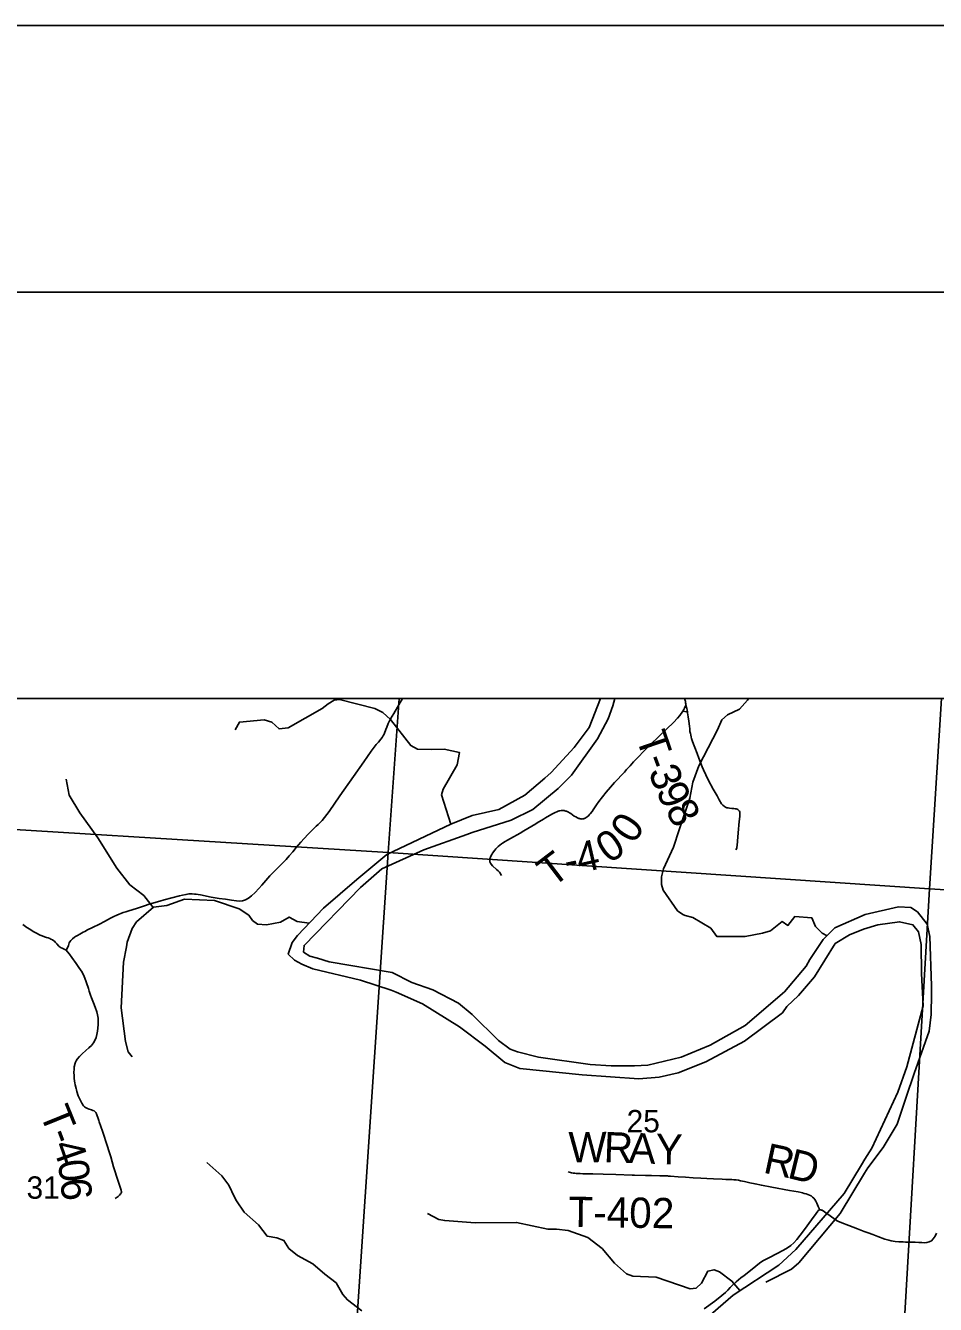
# Model space of a CAD drawing. Extents: x 396.2 to 468.4, y 232.6 to 279.1.
# Drawn here: x 416.062 to 417.769, y 276.722 to 279.121 of the extents above; entities that cross this region are included whole.
import ezdxf

# ---------------------------------------------------------------- set-up
doc = ezdxf.new("R2010")
doc.units = 0
for name, color, linetype in [('Default', 7, 'Continuous'), ('GM_X_Major_River', 7, 'Continuous'), ('GM_X_Minor_River', 7, 'Continuous'), ('GM_X_Section', 7, 'Continuous'), ('GM_X_Section_Text', 7, 'Continuous'), ('GM_X_Township_Road', 7, 'Continuous'), ('GM_X_Township_Road_Text', 7, 'Continuous'), ('SH_Border', 7, 'Continuous'), ('SH_Cut_Line', 7, 'Continuous'), ('TX_P_1', 7, 'Continuous')]:
    doc.layers.add(name, color=color, linetype=linetype)

msp = doc.modelspace()

# ---------------------------------------------------------------- linework, layer by layer
at = {"layer": 'Default'}
msp.add_lwpolyline([(421.9682, 277.8582), (415.7353, 277.8582), (415.7264, 277.732), (415.6501, 276.6818)], dxfattribs=at)
for points in [[(416.7632, 277.8582), (415.744, 277.8582), (415.7301, 277.667), (415.7271, 277.6318), (416.7426, 277.5691)], [(417.7799, 277.8582), (416.7632, 277.8582), (416.7426, 277.5691), (417.7578, 277.5012)], [(418.5596, 277.8582), (417.7799, 277.8582), (417.7578, 277.5012), (418.7866, 277.4374), (418.8114, 277.8417)]]:
    msp.add_lwpolyline(points, close=True, dxfattribs=at)
at = {"layer": 'GM_X_Major_River'}
for points in [[(417.1403, 277.8582), (417.1194, 277.8041), (417.0911, 277.7661), (417.048, 277.7192), (417.036, 277.7086), (416.9989, 277.6769), (416.9501, 277.6498), (416.8998, 277.6386), (416.8601, 277.6225), (416.7398, 277.5655), (416.6834, 277.5187), (416.6211, 277.4649), (416.5724, 277.4135), (416.5626, 277.4006), (416.5551, 277.3785), (416.5664, 277.3672), (416.5805, 277.3597), (416.601, 277.351), (416.6908, 277.3297), (416.7477, 277.3109), (416.7575, 277.3072), (416.8065, 277.2857), (416.8763, 277.2424), (416.9245, 277.2057), (416.9613, 277.1755), (416.989, 277.1642), (417.1065, 277.1525), (417.2122, 277.1449), (417.2504, 277.1481), (417.2864, 277.1562), (417.3382, 277.1765), (417.4105, 277.2155), (417.4819, 277.2685), (417.4902, 277.2807)], [(417.7612, 277.3047), (417.7613, 277.3193), (417.7584, 277.4115), (417.7534, 277.4347), (417.7352, 277.4577), (417.7227, 277.466), (417.6995, 277.4671), (417.6371, 277.4532), (417.5803, 277.4279), (417.5584, 277.4058), (417.5332, 277.3685), (417.526, 277.356), (417.4856, 277.308), (417.4119, 277.2448), (417.3465, 277.2077), (417.292, 277.1855), (417.2296, 277.1704), (417.2046, 277.1688), (417.1606, 277.1694), (417.1212, 277.1715), (417.0242, 277.1856), (416.9852, 277.1953), (416.9711, 277.2006), (416.9491, 277.2168), (416.9001, 277.2652), (416.8743, 277.2867), (416.8261, 277.3116), (416.787, 277.3255), (416.7499, 277.344), (416.6316, 277.364), (416.61, 277.3708), (416.5952, 277.3749), (416.5838, 277.3824), (416.5846, 277.395), (416.6907, 277.5035), (416.7304, 277.5389), (416.8091, 277.5745), (416.89, 277.6033), (416.8999, 277.6067), (416.9733, 277.6298), (417.0138, 277.65), (417.0614, 277.6893), (417.0859, 277.7144), (417.135, 277.7826), (417.155, 277.8198), (417.164, 277.8445), (417.1677, 277.8582)], [(417.4902, 277.2807), (417.5118, 277.3009), (417.542, 277.3363), (417.5808, 277.3983), (417.6073, 277.4151), (417.6338, 277.4255), (417.661, 277.4335), (417.7015, 277.4394), (417.7265, 277.4338), (417.7368, 277.4206), (417.7422, 277.3967), (417.7427, 277.342), (417.7459, 277.2817), (417.7148, 277.1674), (417.6983, 277.1195), (417.6493, 277.0149), (417.6361, 276.994), (417.6301, 276.9834), (417.5973, 276.9294), (417.5067, 276.8243), (417.4749, 276.7953), (417.3895, 276.7388), (417.3283, 276.6855)], [(417.7139, 277.1102), (417.7288, 277.1549), (417.757, 277.2339), (417.7607, 277.2651), (417.7612, 277.3047)], [(417.4504, 276.763), (417.4985, 276.7878), (417.5124, 276.7993), (417.5902, 276.8921), (417.6354, 276.9675), (417.6422, 276.9777), (417.6709, 277.0158), (417.6969, 277.0595), (417.7139, 277.1102)]]:
    msp.add_lwpolyline(points, dxfattribs=at)
at = {"layer": 'GM_X_Minor_River'}
for points in [[(416.8601, 277.6225), (416.8426, 277.6772), (416.8454, 277.6882), (416.8719, 277.7338), (416.8764, 277.7566), (416.8472, 277.763), (416.8229, 277.7626), (416.7971, 277.763), (416.7847, 277.77), (416.747, 277.8191), (416.7323, 277.8319), (416.7173, 277.8397), (416.6514, 277.8561), (416.6408, 277.8548), (416.6296, 277.8481), (416.6185, 277.8395), (416.5546, 277.8031), (416.5378, 277.8011), (416.5243, 277.8138), (416.5099, 277.8182), (416.4635, 277.8139), (416.4554, 277.7995)], [(417.5656, 277.4132), (417.5562, 277.4181), (417.5436, 277.4307), (417.5372, 277.4466), (417.505, 277.4492), (417.4921, 277.4325), (417.4811, 277.4397), (417.4595, 277.4222), (417.4443, 277.418), (417.4117, 277.4115), (417.3655, 277.4118), (417.3587, 277.4118), (417.3473, 277.4274), (417.3136, 277.4471), (417.2995, 277.4509), (417.295, 277.4528), (417.2851, 277.46), (417.2582, 277.4984), (417.2548, 277.509), (417.2552, 277.5234), (417.2586, 277.5387), (417.2772, 277.579), (417.2879, 277.6121), (417.3083, 277.6714), (417.3137, 277.7015), (417.3247, 277.7319), (417.3603, 277.7996), (417.3683, 277.8183), (417.3789, 277.8278), (417.4013, 277.8381), (417.4164, 277.8552), (417.4181, 277.8582)], [(416.3018, 277.4661), (416.2841, 277.4885), (416.2579, 277.5086), (416.2333, 277.5398), (416.1977, 277.5968), (416.164, 277.6439), (416.1439, 277.6769), (416.1386, 277.707)], [(416.5941, 277.4366), (416.5718, 277.4398), (416.5566, 277.4481), (416.5407, 277.4386), (416.5141, 277.4336), (416.4975, 277.4347), (416.488, 277.4416), (416.4808, 277.4518), (416.463, 277.4636), (416.4164, 277.4795), (416.3603, 277.4817), (416.3273, 277.4699), (416.3022, 277.4665), (416.2704, 277.4391), (416.2621, 277.4265), (416.2526, 277.401), (416.2514, 277.3923), (416.2461, 277.3638), (416.2419, 277.2778), (416.2498, 277.2147), (416.2548, 277.1953), (416.2623, 277.1858)], [(416.6932, 276.7095), (416.6663, 276.73), (416.6572, 276.7403), (416.6451, 276.7619), (416.6238, 276.7782), (416.6011, 276.7976), (416.5723, 276.8132), (416.556, 276.8265), (416.5469, 276.8417), (416.5336, 276.8462), (416.5154, 276.8496), (416.4995, 276.8709), (416.4726, 276.8944), (416.4582, 276.9161), (416.4544, 276.9225), (416.4435, 276.9453), (416.4302, 276.9628), (416.4022, 276.9875)], [(417.4017, 276.7479), (417.3869, 276.7654), (417.3636, 276.7828), (417.3537, 276.7864), (417.3419, 276.7842), (417.3302, 276.7616), (417.3198, 276.7519), (417.3088, 276.7509), (417.2449, 276.7726), (417.2013, 276.7744), (417.1896, 276.7787), (417.167, 276.7988), (417.1439, 276.8264), (417.1168, 276.8469), (417.0798, 276.86), (417.0578, 276.8626), (417.0415, 276.8628), (416.9832, 276.8753), (416.9053, 276.8745), (416.8484, 276.8787), (416.8374, 276.8811), (416.8163, 276.892)]]:
    msp.add_lwpolyline(points, dxfattribs=at)
at = {"layer": 'GM_X_Section'}
for points in [[(415.7271, 277.6318), (416.7426, 277.5691), (416.6739, 276.5403), (415.6539, 276.603), (415.6579, 276.653)], [(417.7578, 277.5012), (417.6982, 276.4784), (416.6739, 276.5403), (416.7426, 277.5691)], [(417.7578, 277.5012), (418.7866, 277.4374), (418.7224, 276.4162), (417.6982, 276.4784)]]:
    msp.add_lwpolyline(points, close=True, dxfattribs=at)
at = {"layer": 'GM_X_Township_Road'}
for points in [[(416.0573, 277.4341), (416.0649, 277.4288), (416.0703, 277.4253), (416.0765, 277.4214), (416.0804, 277.4193), (416.0841, 277.4174), (416.0874, 277.4155), (416.0895, 277.4145), (416.0932, 277.4129), (416.0978, 277.4112), (416.1017, 277.4101), (416.1049, 277.4091), (416.1078, 277.4079), (416.11, 277.4069), (416.1129, 277.4053), (416.1152, 277.4038), (416.117, 277.4022), (416.1185, 277.4005), (416.121, 277.3979), (416.1248, 277.3938), (416.1281, 277.3911), (416.1308, 277.3897), (416.1383, 277.3861), (416.1408, 277.3906), (416.1427, 277.395), (416.1433, 277.3972), (416.1444, 277.3998), (416.1455, 277.4019), (416.1471, 277.4043), (416.1491, 277.4063), (416.1505, 277.4076), (416.1543, 277.4105), (416.1558, 277.4115), (416.1598, 277.4139), (416.1642, 277.4163), (416.1706, 277.4197), (416.1736, 277.4213), (416.1785, 277.424), (416.1878, 277.4289), (416.2009, 277.435), (416.2105, 277.4398), (416.2216, 277.4458), (416.2279, 277.4494), (416.2333, 277.452), (416.2377, 277.4537), (416.2413, 277.4551), (416.2454, 277.4567), (416.2502, 277.4582), (416.2563, 277.4601), (416.2701, 277.4643), (416.2855, 277.4695), (416.2942, 277.4724), (416.3141, 277.4783), (416.3221, 277.4804), (416.351, 277.4877), (416.3569, 277.4893), (416.3635, 277.4907), (416.3685, 277.4915), (416.3721, 277.4917), (416.3747, 277.4917), (416.3789, 277.4914), (416.3821, 277.4909), (416.3858, 277.4904), (416.3902, 277.4896), (416.4103, 277.4856), (416.4256, 277.4831), (416.4373, 277.4815), (416.4484, 277.4799), (416.4582, 277.4786), (416.4637, 277.4782), (416.4692, 277.4788), (416.4749, 277.4807), (416.4802, 277.4838), (416.4861, 277.4882), (416.4929, 277.4945), (416.4997, 277.5016), (416.5055, 277.5081), (416.5128, 277.5165), (416.5207, 277.5253), (416.528, 277.533), (416.5425, 277.5475), (416.5486, 277.5537), (416.5512, 277.5563), (416.5569, 277.5628), (416.5637, 277.5708), (416.5701, 277.5784), (416.5789, 277.5888), (416.5851, 277.5958), (416.5923, 277.6035), (416.6023, 277.6137), (416.6073, 277.6185), (416.6109, 277.6218), (416.6188, 277.6296), (416.6232, 277.6348), (416.6316, 277.6461), (416.652, 277.6758), (416.6772, 277.7118), (416.6966, 277.7396), (416.7105, 277.7594), (416.7201, 277.7717), (416.724, 277.7765), (416.7288, 277.7822), (416.7309, 277.785), (416.7326, 277.7876), (416.734, 277.7901), (416.7353, 277.793), (416.7362, 277.7951), (416.7374, 277.7983), (416.7379, 277.7998), (416.7396, 277.8047), (416.7423, 277.8111), (416.7466, 277.82), (416.7528, 277.8302), (416.7692, 277.8582)], [(417.108, 277.6323), (417.1088, 277.6325), (417.1098, 277.6328), (417.1108, 277.6331), (417.1116, 277.6335), (417.1138, 277.6349), (417.1153, 277.636), (417.1178, 277.6383), (417.1192, 277.6397), (417.1209, 277.6416), (417.1247, 277.6463), (417.1268, 277.6493), (417.1332, 277.6588), (417.1375, 277.6648), (417.1442, 277.6738), (417.1509, 277.6822), (417.1592, 277.6919), (417.1668, 277.7004), (417.1854, 277.7202), (417.1896, 277.7247), (417.1961, 277.7321), (417.2027, 277.7392), (417.2125, 277.7496), (417.2206, 277.7581), (417.229, 277.7663), (417.2352, 277.7724), (417.2496, 277.7866), (417.2647, 277.8011), (417.2773, 277.8133), (417.2848, 277.821), (417.2893, 277.8265), (417.295, 277.8345), (417.2968, 277.8376), (417.2979, 277.84), (417.3004, 277.846)], [(417.3004, 277.846), (417.3004, 277.8482), (417.3003, 277.8498), (417.3002, 277.8514), (417.3, 277.8523), (417.2997, 277.8537), (417.2993, 277.8546), (417.2986, 277.8562), (417.2977, 277.8577), (417.2974, 277.8582)], [(417.3946, 277.5741), (417.3954, 277.576), (417.3961, 277.5779), (417.3965, 277.5796), (417.3969, 277.5826), (417.3977, 277.5907), (417.3988, 277.6061), (417.4006, 277.6277), (417.4011, 277.6321), (417.4017, 277.6374), (417.4019, 277.6404), (417.402, 277.6434), (417.4017, 277.6452), (417.4012, 277.6466), (417.4008, 277.6473), (417.4001, 277.6483), (417.3994, 277.649), (417.3982, 277.6499), (417.3966, 277.6506), (417.395, 277.6511), (417.393, 277.6514), (417.3907, 277.6517), (417.3867, 277.6521), (417.3824, 277.6525), (417.3798, 277.6528), (417.3773, 277.6533), (417.3762, 277.6537), (417.3752, 277.6541), (417.3735, 277.6551), (417.3723, 277.656), (417.37, 277.658), (417.3678, 277.6609), (417.3633, 277.6683), (417.3594, 277.6753), (417.3521, 277.6883), (417.3426, 277.7056), (417.3379, 277.7151), (417.3339, 277.7241), (417.3312, 277.73), (417.3248, 277.746), (417.3216, 277.755), (417.3176, 277.7664), (417.3165, 277.7697), (417.3134, 277.7778), (417.3121, 277.781), (417.3113, 277.7834), (417.3108, 277.7854), (417.3097, 277.7899), (417.3092, 277.7924), (417.3084, 277.7965), (417.3079, 277.801), (417.3072, 277.8064), (417.3061, 277.8156), (417.305, 277.8237), (417.3044, 277.8274), (417.3038, 277.8311), (417.3035, 277.8329), (417.3029, 277.8361), (417.3022, 277.8401), (417.3019, 277.8414), (417.3014, 277.8435), (417.301, 277.8446), (417.3004, 277.846)], [(417.295, 277.8345), (417.3019, 277.8331), (417.3035, 277.8329)], [(416.9547, 277.526), (416.9531, 277.5291), (416.9522, 277.5305), (416.951, 277.5322), (416.9485, 277.5349), (416.9458, 277.5373), (416.938, 277.5444), (416.9353, 277.5476), (416.9342, 277.5492), (416.9335, 277.5508), (416.9331, 277.5521), (416.9329, 277.553), (416.9328, 277.554), (416.9328, 277.5554), (416.9329, 277.5567), (416.9332, 277.5579), (416.9336, 277.5593), (416.934, 277.5607), (416.9347, 277.5622), (416.9367, 277.5655), (416.9382, 277.5679), (416.9422, 277.5734), (416.9443, 277.5759), (416.9469, 277.5787), (416.9489, 277.5808), (416.9515, 277.583), (416.9548, 277.5855), (416.9571, 277.587), (416.9617, 277.5899), (416.966, 277.5923), (416.9773, 277.5984), (416.9843, 277.6024), (416.9899, 277.6055), (416.9969, 277.6097), (417.019, 277.6233), (417.0217, 277.6249), (417.0338, 277.632), (417.0375, 277.6343), (417.0493, 277.6412), (417.0528, 277.6432), (417.0558, 277.6446), (417.0584, 277.6458), (417.0612, 277.6469), (417.063, 277.6474), (417.0645, 277.6477), (417.0669, 277.648), (417.0682, 277.648), (417.0692, 277.648), (417.0709, 277.6479), (417.0724, 277.6478), (417.074, 277.6475), (417.0756, 277.6471), (417.0767, 277.6467), (417.078, 277.6461), (417.0806, 277.6448), (417.0823, 277.6439), (417.0847, 277.6425), (417.088, 277.6401), (417.0915, 277.6377), (417.0945, 277.6359), (417.0977, 277.6343), (417.0999, 277.6333), (417.1011, 277.6329), (417.1024, 277.6326), (417.1033, 277.6324), (417.1042, 277.6322), (417.1059, 277.6321), (417.1072, 277.6322), (417.108, 277.6323)], [(416.1383, 277.3861), (416.1412, 277.383), (416.1446, 277.3783), (416.1489, 277.3721), (416.1571, 277.3608), (416.1622, 277.3537), (416.1683, 277.3446), (416.1723, 277.3366), (416.1756, 277.3284), (416.1769, 277.3246), (416.1802, 277.3142), (416.1819, 277.309), (416.1843, 277.3018), (416.1863, 277.2965), (416.1897, 277.2875), (416.1931, 277.2789), (416.196, 277.2707), (416.1975, 277.2646), (416.1985, 277.2585), (416.1988, 277.2516), (416.1986, 277.2469), (416.1981, 277.2395), (416.1974, 277.2343), (416.1962, 277.2276), (416.1947, 277.2223), (416.1923, 277.2166), (416.1897, 277.2122), (416.1862, 277.2075), (416.1813, 277.2027), (416.1753, 277.1977), (416.1683, 277.1917), (416.1633, 277.1867), (416.159, 277.1813), (416.1575, 277.1787), (416.1562, 277.1762), (416.1554, 277.1741), (416.1537, 277.1671), (416.1533, 277.1628), (416.153, 277.1566), (416.1532, 277.1508), (416.1537, 277.1461), (416.1544, 277.1405), (416.1549, 277.1374), (416.1556, 277.1336), (416.157, 277.1268), (416.1578, 277.1238), (416.1585, 277.1211), (416.1613, 277.1129), (416.1645, 277.1056), (416.1679, 277.0991), (416.1712, 277.0941), (416.1726, 277.0924), (416.1747, 277.0907), (416.1761, 277.09), (416.1788, 277.0891), (416.1817, 277.088), (416.1857, 277.0864), (416.1887, 277.0852), (416.1907, 277.0844), (416.1925, 277.0834)], [(416.2302, 276.92), (416.2343, 276.9228), (416.236, 276.9242), (416.2388, 276.9267), (416.2406, 276.9287), (416.2414, 276.9299), (416.2417, 276.9305), (416.2421, 276.9318), (416.2421, 276.9325), (416.2421, 276.9333), (416.2418, 276.9349), (416.2416, 276.9357), (416.2408, 276.938), (416.2391, 276.9433), (416.2358, 276.953), (416.2272, 276.9794), (416.222, 276.9984), (416.2186, 277.0095), (416.2159, 277.0179), (416.2069, 277.0465), (416.2036, 277.0553), (416.2006, 277.064), (416.1997, 277.0667), (416.1978, 277.0724), (416.1969, 277.0754), (416.1955, 277.079), (416.194, 277.0816), (416.1925, 277.0834)], [(417.0799, 276.97), (417.0841, 276.9689), (417.0863, 276.9684), (417.0894, 276.9679), (417.0924, 276.9675), (417.0949, 276.9672), (417.098, 276.9671), (417.1023, 276.9669), (417.1076, 276.9668), (417.1169, 276.9668), (417.1262, 276.9667), (417.1455, 276.9659), (417.1692, 276.9651), (417.1999, 276.9642), (417.2028, 276.9641), (417.2046, 276.964), (417.2251, 276.9633), (417.2363, 276.9631), (417.2519, 276.9629), (417.2588, 276.9627), (417.2662, 276.9625), (417.2679, 276.9624), (417.2699, 276.9624), (417.2721, 276.9622), (417.2863, 276.961), (417.3, 276.9603), (417.3144, 276.9592), (417.3289, 276.9585), (417.3397, 276.9576), (417.3528, 276.9568), (417.369, 276.9563), (417.3758, 276.9561), (417.382, 276.956), (417.3869, 276.9557), (417.3909, 276.9554), (417.3949, 276.955), (417.3992, 276.9543), (417.4034, 276.9535), (417.4106, 276.9521), (417.4206, 276.9498), (417.4306, 276.9475), (417.4423, 276.9451), (417.4617, 276.9415), (417.4951, 276.9353), (417.511, 276.9325), (417.5167, 276.9313), (417.5195, 276.9306), (417.5227, 276.9299), (417.5262, 276.9287), (417.5297, 276.9275), (417.5323, 276.9264), (417.5354, 276.9251), (417.5384, 276.923), (417.5405, 276.9208), (417.5424, 276.9183), (417.5442, 276.915), (417.5463, 276.9113), (417.5478, 276.9083), (417.5491, 276.905), (417.5504, 276.9016), (417.5513, 276.8987)], [(417.335, 276.713), (417.3552, 276.7275), (417.3682, 276.738), (417.3747, 276.7436), (417.3774, 276.7462), (417.3794, 276.7485), (417.3836, 276.7534), (417.388, 276.7579), (417.3948, 276.764), (417.4037, 276.7713), (417.41, 276.776), (417.4217, 276.7852), (417.4318, 276.7934), (417.4356, 276.7966), (417.4412, 276.8006), (417.4465, 276.8038), (417.4575, 276.8095), (417.4707, 276.8163), (417.4839, 276.8234), (417.4913, 276.8279), (417.4974, 276.8322), (417.5029, 276.8372), (417.5089, 276.8435), (417.5152, 276.8512), (417.5234, 276.8621), (417.5366, 276.8801), (417.545, 276.8921), (417.5481, 276.8966), (417.5491, 276.8975), (417.5502, 276.8983), (417.5513, 276.8987), (417.5527, 276.899), (417.554, 276.8989), (417.5552, 276.8986), (417.5564, 276.8981), (417.5605, 276.8955), (417.5715, 276.8874), (417.5807, 276.8806), (417.5829, 276.8792), (417.5855, 276.8778), (417.5933, 276.8747), (417.6061, 276.8698), (417.6226, 276.8632), (417.6352, 276.8585), (417.6426, 276.8559), (417.6515, 276.8524), (417.6609, 276.8489), (417.6737, 276.8442), (417.6813, 276.8418), (417.6856, 276.8409), (417.6896, 276.8402), (417.6935, 276.8396), (417.7003, 276.8389), (417.7042, 276.8388), (417.7083, 276.8387), (417.7126, 276.8386), (417.7305, 276.8383), (417.7375, 276.8378), (417.7434, 276.8375), (417.7483, 276.8373), (417.7527, 276.8377), (417.7569, 276.8387), (417.7612, 276.841), (417.7647, 276.8445), (417.768, 276.8497), (417.7709, 276.8551)]]:
    msp.add_lwpolyline(points, dxfattribs=at)
at = {"layer": 'SH_Border'}
msp.add_lwpolyline([(397.7027, 278.6206), (429.7027, 278.6206), (429.7027, 257.6206), (397.7027, 257.6206)], close=True, dxfattribs=at)
at = {"layer": 'SH_Cut_Line'}
msp.add_lwpolyline([(396.2027, 257.1206), (430.2027, 257.1206), (430.2027, 279.1206), (396.2027, 279.1206)], close=True, dxfattribs=at)
msp.add_lwpolyline([(422.4135, 277.8582), (413.8513, 277.8582), (413.8513, 270.6726)], dxfattribs=at)
at = {"layer": 'TX_P_1'}
msp.add_line((427.4513, 277.8582), (413.8513, 277.8582), dxfattribs=at)

# ---------------------------------------------------------------- texts
at = {"layer": 'GM_X_Section_Text'}
for s, p in [('25', (417.1896, 277.0444)), ('31', (416.0642, 276.9198))]:
    msp.add_text(s, height=0.04186, rotation=0, dxfattribs=at).set_placement(p)
at = {"layer": 'GM_X_Township_Road_Text'}
for s, height, rotation, p in [('T', 0.0568, 288.8388, (417.2065, 277.786)), ('-', 0.0568, 290.5763, (417.2209, 277.744)), ('3', 0.0568, 291.8045, (417.2295, 277.7209)), ('9', 0.0568, 294.5091, (417.2437, 277.6857)), ('8', 0.0568, 299.7216, (417.2608, 277.6488)), ('0', 0.0568, 55.7708, (417.2021, 277.5831)), ('0', 0.0568, 34.132, (417.1567, 277.5471)), ('T', 0.0568, 37.3224, (417.0501, 277.5021)), ('4', 0.0568, 12.8946, (417.1016, 277.5302)), ('-', 0.0568, 12.0991, (417.078, 277.5251)), ('T', 0.0568, 292.068, (416.088, 277.0806)), ('-', 0.0568, 290.5373, (416.1038, 277.0416)), ('W', 0.0568, 0.4938, (417.0808, 276.9879)), ('4', 0.0568, 289.1401, (416.1119, 277.0201)), ('R', 0.0568, 358.0502, (417.146, 276.9885)), ('A', 0.0568, 357.9615, (417.1926, 276.9869)), ('Y', 0.0568, 358.5071, (417.2432, 276.9851)), ('R', 0.0568, 347.8971, (417.4438, 276.9691)), ('D', 0.0568, 346.1564, (417.489, 276.9594)), ('0', 0.0568, 277.5204, (416.1226, 276.99)), ('6', 0.0568, 276.1368, (416.1272, 276.9557)), ('T-402', 0.05682, 359.1763, (417.0801, 276.867))]:
    msp.add_text(s, height=height, rotation=rotation, dxfattribs=at).set_placement(p)

doc.saveas('drawing.dxf')
